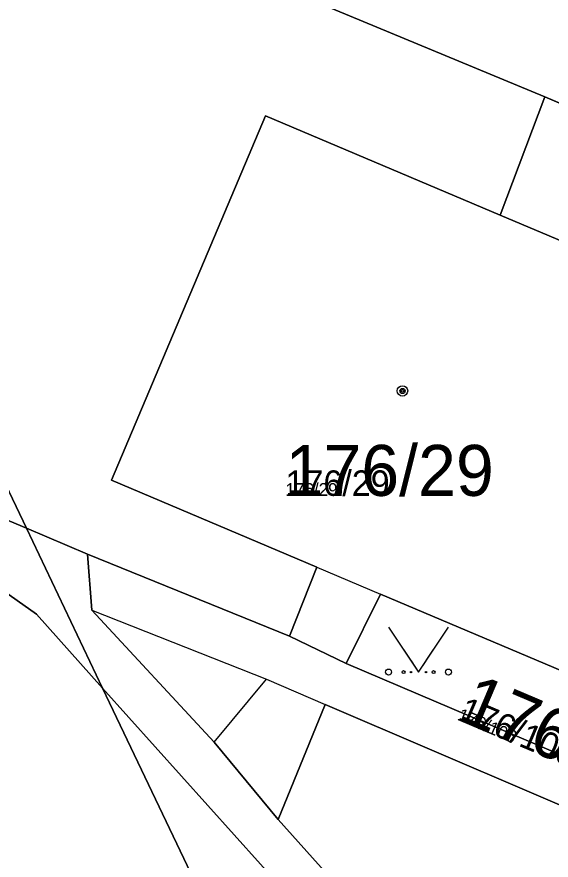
# Model space of a CAD drawing. Extents: x -759873 to -758487, y -975024 to -973516.
# Drawn here: x -759779.53 to -759761.69, y -974967.38 to -974939.25 of the extents above; entities that cross this region are included whole.
import ezdxf

# ---------------------------------------------------------------- set-up
doc = ezdxf.new("R2010")
doc.units = 0
for name, color, linetype in [('KAT_02_hranice parcel', 7, 'Continuous'), ('KAT_03_1000_st čísla parcelní', 7, 'Continuous'), ('KAT_03_1000_čísla parcelní', 7, 'Continuous'), ('KAT_03_250_st čísla parcelní', 7, 'Continuous'), ('KAT_03_250_čísla parcelní', 7, 'Continuous'), ('KAT_03_500_st čísla parcelní', 7, 'Continuous'), ('KAT_03_500_čísla parcelní', 7, 'Continuous'), ('KAT_04_vnitřní kresba', 7, 'Continuous'), ('KAT_05_1000_značky kultur', 7, 'Continuous'), ('KAT_05_250_značky kultur', 7, 'Continuous'), ('KAT_05_500_značky kultur', 7, 'Continuous'), ('KAT_07_1000_značky budov', 7, 'Continuous'), ('KAT_07_250_značky budov', 7, 'Continuous'), ('KAT_07_500_značky budov', 7, 'Continuous'), ('KAT_14_plocha_budovy', 7, 'Continuous'), ('KAT_14_plocha_pozemek', 7, 'Continuous')]:
    doc.layers.add(name, color=color, linetype=linetype)

msp = doc.modelspace()

# ---------------------------------------------------------------- linework, layer by layer
at = {"layer": 'KAT_02_hranice parcel'}
for p, q in [((-759759.43, -974942.97), (-759761.9, -974941.92)), ((-759779.21, -974956.31), (-759776.67, -974961.64)), ((-759779.21, -974956.31), (-759777.17, -974957.17)), ((-759777.17, -974957.17), (-759770.43, -974959.91)), ((-759770.43, -974959.91), (-759768.53, -974960.82)), ((-759768.53, -974960.82), (-759757.28, -974965.62)), ((-759776.67, -974961.64), (-759756.15, -975004.6))]:
    msp.add_line(p, q, dxfattribs=at)
for points in [[(-759801.21, -974917.09), (-759791.2, -974931.2), (-759779.21, -974956.31)], [(-759801.36, -974917.91), (-759793.92, -974932.14), (-759782.72, -974953.53), (-759781.6, -974955.18), (-759780.67, -974955.7), (-759779.21, -974956.31)], [(-759776.67, -974961.64), (-759778.87, -974959.18), (-759782.83, -974956.39), (-759784.21, -974954.04), (-759795.39, -974932.77), (-759801.82, -974920.4)], [(-759761.9, -974941.92), (-759771.3, -974938.01), (-759767.72, -974934.65), (-759753.04, -974941.19), (-759730.59, -974950.55), (-759729.44, -974947.87), (-759725.05, -974949.69), (-759726.06, -974952.43), (-759721.2, -974954.46)], [(-759761.9, -974941.92), (-759763.4, -974945.86), (-759771.23, -974942.55), (-759776.37, -974954.71), (-759769.51, -974957.61), (-759770.43, -974959.91)], [(-759777.17, -974957.17), (-759777.02, -974959.04), (-759772.94, -974963.45), (-759770.81, -974966.03)], [(-759768.53, -974960.82), (-759767.39, -974958.51), (-759759.58, -974961.81)], [(-759776.67, -974961.64), (-759760.85, -974979.26), (-759749.8, -974991.38)], [(-759770.81, -974966.03), (-759769.24, -974962.19), (-759758.63, -974966.73), (-759760.18, -974970.6), (-759752.01, -974974.08), (-759750.27, -974970.29), (-759722.49, -974982.07), (-759724.08, -974985.84), (-759715.79, -974989.44), (-759714.25, -974985.59), (-759695.75, -974993.4), (-759687.1, -974995.48)], [(-759740.23, -974999.88), (-759748.8, -974990.42), (-759759.81, -974978.29), (-759770.81, -974966.03)]]:
    msp.add_lwpolyline(points, dxfattribs=at)
at = {"layer": 'KAT_04_vnitřní kresba'}
for p, q in [((-759763.4, -974945.86), (-759761.05, -974946.85)), ((-759769.51, -974957.61), (-759767.39, -974958.51)), ((-759777.02, -974959.04), (-759771.19, -974961.34)), ((-759772.94, -974963.45), (-759771.19, -974961.34)), ((-759771.19, -974961.34), (-759769.24, -974962.19))]:
    msp.add_line(p, q, dxfattribs=at)
at = {"layer": 'KAT_05_1000_značky kultur'}
msp.add_lwpolyline([(-759767.12, -974959.609), (-759766.12, -974961.11), (-759765.12, -974959.609)], dxfattribs=at)
for centre in [(-759767.12, -974961.109), (-759765.12, -974961.109)]:
    msp.add_circle(centre, 0.1, dxfattribs=at)
at = {"layer": 'KAT_05_250_značky kultur'}
msp.add_lwpolyline([(-759766.37, -974960.735), (-759766.12, -974961.11), (-759765.87, -974960.735)], dxfattribs=at)
for centre in [(-759766.37, -974961.11), (-759765.87, -974961.11)]:
    msp.add_circle(centre, 0.025, dxfattribs=at)
at = {"layer": 'KAT_05_500_značky kultur'}
msp.add_lwpolyline([(-759766.62, -974960.36), (-759766.12, -974961.11), (-759765.62, -974960.36)], dxfattribs=at)
for centre in [(-759766.62, -974961.11), (-759765.62, -974961.11)]:
    msp.add_circle(centre, 0.05, dxfattribs=at)
at = {"layer": 'KAT_07_1000_značky budov'}
msp.add_circle((-759766.657, -974951.729), 0.175, dxfattribs=at)
at = {"layer": 'KAT_07_250_značky budov'}
msp.add_circle((-759766.652, -974951.73), 0.0437, dxfattribs=at)
at = {"layer": 'KAT_07_500_značky budov'}
msp.add_circle((-759766.653, -974951.73), 0.0875, dxfattribs=at)
at = {"layer": 'KAT_14_plocha_budovy'}
msp.add_lwpolyline([(-759729.62, -974974.47), (-759724.48, -974962.32), (-759731.18, -974959.49), (-759733.55, -974958.48), (-759741.18, -974955.26), (-759748.09, -974952.33), (-759750.59, -974951.28), (-759757.76, -974948.25), (-759761.05, -974946.85), (-759763.4, -974945.86), (-759771.23, -974942.55), (-759776.37, -974954.71), (-759769.51, -974957.61), (-759767.39, -974958.51), (-759759.58, -974961.81), (-759756.25, -974963.22), (-759754.1, -974964.12), (-759746.32, -974967.41), (-759739.63, -974970.24), (-759737.55, -974971.12)], close=True, dxfattribs=at)
at = {"layer": 'KAT_14_plocha_pozemek'}
for points in [[(-759761.9, -974941.92), (-759771.3, -974938.01), (-759767.72, -974934.65), (-759753.04, -974941.19), (-759730.59, -974950.55), (-759729.44, -974947.87), (-759725.05, -974949.69), (-759726.06, -974952.43), (-759721.2, -974954.46), (-759717.87, -974946.11), (-759725.37, -974940.74), (-759728.55, -974937.97), (-759754.58, -974925.88), (-759787.25, -974910.64), (-759799, -974905.15), (-759801.21, -974917.09), (-759791.2, -974931.2), (-759779.21, -974956.31), (-759777.17, -974957.17), (-759770.43, -974959.91), (-759769.51, -974957.61), (-759776.37, -974954.71), (-759771.23, -974942.55), (-759763.4, -974945.86)], [(-759801.36, -974917.91), (-759793.92, -974932.14), (-759782.72, -974953.53), (-759781.6, -974955.18), (-759780.67, -974955.7), (-759779.21, -974956.31), (-759791.2, -974931.2), (-759801.21, -974917.09)], [(-759801.82, -974920.4), (-759795.39, -974932.77), (-759784.21, -974954.04), (-759782.83, -974956.39), (-759778.87, -974959.18), (-759776.67, -974961.64), (-759779.21, -974956.31), (-759780.67, -974955.7), (-759781.6, -974955.18), (-759782.72, -974953.53), (-759793.92, -974932.14), (-759801.36, -974917.91)], [(-759759.58, -974961.81), (-759757.01, -974955.73), (-759760.33, -974954.33), (-759757.76, -974948.25), (-759761.05, -974946.85), (-759759.43, -974942.97), (-759761.9, -974941.92), (-759763.4, -974945.86), (-759771.23, -974942.55), (-759776.37, -974954.71), (-759769.51, -974957.61), (-759770.43, -974959.91), (-759768.53, -974960.82), (-759767.39, -974958.51)], [(-759748.8, -974990.42), (-759759.81, -974978.29), (-759770.81, -974966.03), (-759772.94, -974963.45), (-759777.02, -974959.04), (-759777.17, -974957.17), (-759779.21, -974956.31), (-759776.67, -974961.64), (-759760.85, -974979.26), (-759749.8, -974991.38), (-759741.85, -975000.36), (-759740.23, -974999.88)], [(-759757.28, -974965.62), (-759756.25, -974963.22), (-759759.58, -974961.81), (-759767.39, -974958.51), (-759768.53, -974960.82)], [(-759753.64, -975003.86), (-759752.46, -975003.34), (-759756.88, -974995.21), (-759749.8, -974991.38), (-759760.85, -974979.26), (-759776.67, -974961.64), (-759756.15, -975004.6)], [(-759727.3, -974996.05), (-759719.75, -974996.3), (-759712.2, -974997), (-759687.1, -974995.48), (-759695.75, -974993.4), (-759714.25, -974985.59), (-759715.79, -974989.44), (-759724.08, -974985.84), (-759722.49, -974982.07), (-759750.27, -974970.29), (-759752.01, -974974.08), (-759760.18, -974970.6), (-759758.63, -974966.73), (-759769.24, -974962.19), (-759770.81, -974966.03), (-759759.81, -974978.29), (-759748.8, -974990.42), (-759740.23, -974999.88)]]:
    msp.add_lwpolyline(points, close=True, dxfattribs=at)
for points in [[(-759756.15, -975004.6), (-759776.67, -974961.64), (-759778.87, -974959.18), (-759782.83, -974956.39), (-759784.21, -974954.04), (-759795.39, -974932.77)], [(-759707.59, -974960.11), (-759719.7, -974955.06), (-759721.2, -974954.46), (-759726.06, -974952.43), (-759725.05, -974949.69), (-759729.44, -974947.87), (-759730.59, -974950.55), (-759753.04, -974941.19), (-759767.72, -974934.65), (-759771.3, -974938.01), (-759761.9, -974941.92), (-759759.43, -974942.97), (-759748.5, -974947.49), (-759746.14, -974948.5), (-759731.88, -974954.47), (-759729.47, -974955.44), (-759715, -974961.43), (-759712.6, -974962.44)], [(-759710.53, -974985.47), (-759721.86, -974980.66), (-759723.78, -974979.84), (-759738.78, -974973.41), (-759740.59, -974972.63), (-759755.33, -974966.36), (-759757.28, -974965.62), (-759768.53, -974960.82), (-759770.43, -974959.91), (-759777.17, -974957.17), (-759777.02, -974959.04), (-759772.94, -974963.45), (-759770.81, -974966.03), (-759769.24, -974962.19), (-759758.63, -974966.73), (-759760.18, -974970.6), (-759752.01, -974974.08), (-759750.27, -974970.29), (-759722.49, -974982.07), (-759724.08, -974985.84), (-759715.79, -974989.44), (-759714.25, -974985.59), (-759695.75, -974993.4)]]:
    msp.add_lwpolyline(points, dxfattribs=at)

# ---------------------------------------------------------------- texts
at = {"layer": 'KAT_03_1000_st čísla parcelní'}
msp.add_text('176/29', height=1.7, dxfattribs=at).set_placement((-759770.56, -974955.23))
at = {"layer": 'KAT_03_1000_čísla parcelní'}
msp.add_text('176/106', height=1.7, rotation=337, dxfattribs=at).set_placement((-759764.852, -974962.692))
at = {"layer": 'KAT_03_250_st čísla parcelní'}
msp.add_text('176/29', height=0.425, dxfattribs=at).set_placement((-759770.56, -974955.23))
at = {"layer": 'KAT_03_250_čísla parcelní'}
msp.add_text('176/106', height=0.425, rotation=337, dxfattribs=at).set_placement((-759764.852, -974962.692))
at = {"layer": 'KAT_03_500_st čísla parcelní'}
msp.add_text('176/29', height=0.85, dxfattribs=at).set_placement((-759770.56, -974955.23))
at = {"layer": 'KAT_03_500_čísla parcelní'}
msp.add_text('176/106', height=0.85, rotation=337, dxfattribs=at).set_placement((-759764.852, -974962.692))

doc.saveas('drawing.dxf')
